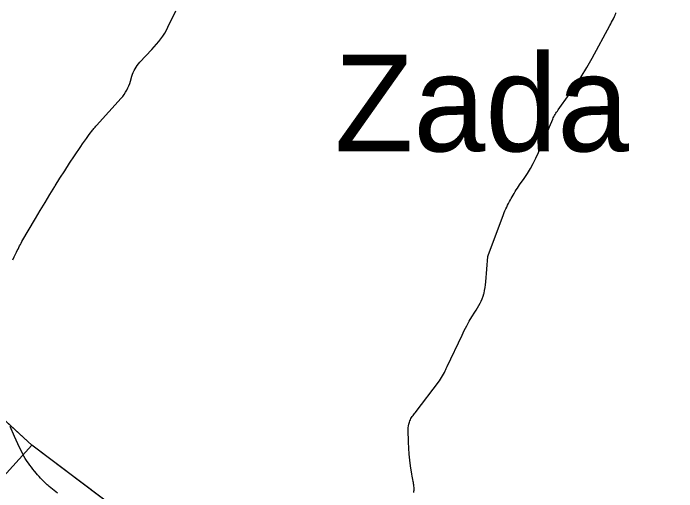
# Model space of a CAD drawing. Extents: x -629976 to -626966, y -1086511 to -1082952.
# Drawn here: x -629290.8 to -629174.2, y -1086163 to -1086079 of the extents above; entities that cross this region are included whole.
import ezdxf

# ---------------------------------------------------------------- set-up
doc = ezdxf.new("R2010")
doc.units = 0
for name, color, linetype in [('01_MÍSTNÍ_NÁZVY', 7, 'Continuous'), ('01_OBVOD PÚ', 7, 'Continuous'), ('01_SPRÁV_HRANICE', 7, 'Continuous'), ('01_VRSTEVNICE', 7, 'Continuous'), ('02_KULTURY STAV', 7, 'Continuous'), ('04_ZPF_OP_ORGAN', 7, 'Continuous')]:
    doc.layers.add(name, color=color, linetype=linetype)

msp = doc.modelspace()

# ---------------------------------------------------------------- linework, layer by layer
at = {"layer": '01_OBVOD PÚ'}
msp.add_lwpolyline([(-629018.08, -1086166.52), (-629041.66, -1086200.2), (-629067.51, -1086228.26), (-629069.33, -1086229.14), (-629087.1, -1086237.74), (-629120.75, -1086241.45), (-629122.84, -1086241.29), (-629134.67, -1086240.38), (-629143.31, -1086237.7), (-629155.05, -1086234.05), (-629163.08, -1086231.74), (-629174.67, -1086228.42), (-629203.15, -1086217.26), (-629215.64, -1086208.09), (-629217.4, -1086206.8), (-629237.51, -1086193.06), (-629238.46, -1086192.41), (-629270.92, -1086167.34), (-629287.56, -1086154.79), (-629303.24, -1086140.47)], dxfattribs=at)
at = {"layer": '01_SPRÁV_HRANICE'}
for p, q in [((-629287.56, -1086154.79), (-629303.24, -1086140.47)), ((-629270.92, -1086167.34), (-629287.56, -1086154.79))]:
    msp.add_line(p, q, dxfattribs=at)
msp.add_lwpolyline([(-629287.56, -1086154.79), (-629320.54, -1086191.18), (-629326.93, -1086197.96), (-629343.16, -1086215.19), (-629354.7, -1086227.44), (-629377.38, -1086206.8), (-629383.75, -1086214.59), (-629406.77, -1086242.76), (-629379.65, -1086273.09), (-629372.5, -1086281.08), (-629369.07, -1086285.03)], dxfattribs=at)
at = {"layer": '01_VRSTEVNICE'}
for points in [[(-629271.07, -1086092.84), (-629270.86, -1086092.46), (-629270.67, -1086092.07), (-629270.5, -1086091.67), (-629270.35, -1086091.27), (-629270.22, -1086090.85), (-629269.98, -1086090.01), (-629269.87, -1086089.67), (-629269.74, -1086089.34), (-629269.59, -1086089.02), (-629269.42, -1086088.7), (-629269.23, -1086088.4), (-629269.03, -1086088.11), (-629268.81, -1086087.83), (-629268.57, -1086087.57), (-629266.44, -1086085.3), (-629266.03, -1086084.85), (-629265.63, -1086084.4), (-629265.25, -1086083.93), (-629264.88, -1086083.46), (-629264.53, -1086082.97), (-629264.2, -1086082.47), (-629263.9, -1086081.95), (-629263.63, -1086081.42), (-629262.22, -1086078.5)], [(-629215.18, -1086142.37), (-629215.01, -1086142.05), (-629214.94, -1086141.92), (-629214.88, -1086141.78), (-629214.82, -1086141.65), (-629214.76, -1086141.51), (-629214.7, -1086141.37), (-629214.64, -1086141.24), (-629214.58, -1086141.1), (-629214.52, -1086140.97), (-629211.93, -1086135.5), (-629211.53, -1086134.67), (-629211.1, -1086133.85), (-629210.65, -1086133.05), (-629210.18, -1086132.26), (-629209.69, -1086131.47), (-629209.45, -1086131.08), (-629209.22, -1086130.69), (-629208.99, -1086130.29), (-629208.76, -1086129.9), (-629208.56, -1086129.5), (-629208.37, -1086129.09), (-629208.22, -1086128.66), (-629208.09, -1086128.23), (-629208.06, -1086128.13), (-629207.95, -1086127.63), (-629207.85, -1086127.14), (-629207.78, -1086126.64), (-629207.73, -1086126.14), (-629207.36, -1086121.66), (-629207.36, -1086121.64), (-629207.35, -1086121.61), (-629207.35, -1086121.59), (-629207.35, -1086121.56), (-629207.34, -1086121.55), (-629207.34, -1086121.53), (-629207.34, -1086121.51), (-629207.33, -1086121.5), (-629207.33, -1086121.48), (-629204.65, -1086114.31), (-629204.52, -1086113.97), (-629204.38, -1086113.64), (-629204.23, -1086113.32), (-629204.07, -1086112.99), (-629203.91, -1086112.67), (-629203.75, -1086112.35), (-629203.58, -1086112.04), (-629203.41, -1086111.72), (-629203.3, -1086111.51), (-629203.13, -1086111.2), (-629202.96, -1086110.89), (-629202.78, -1086110.59), (-629202.59, -1086110.28), (-629202.4, -1086109.98), (-629202.2, -1086109.69), (-629202, -1086109.39), (-629201.8, -1086109.1), (-629201.01, -1086107.98), (-629200.43, -1086107.12), (-629199.89, -1086106.24), (-629199.4, -1086105.32), (-629198.94, -1086104.39), (-629198.04, -1086102.42), (-629197.65, -1086101.54), (-629197.27, -1086100.67), (-629196.9, -1086099.78), (-629196.53, -1086098.9), (-629195.99, -1086097.56), (-629195.9, -1086097.34), (-629195.8, -1086097.13), (-629195.68, -1086096.92), (-629195.56, -1086096.72), (-629195.43, -1086096.52), (-629195.3, -1086096.32), (-629195.17, -1086096.12), (-629195.03, -1086095.93), (-629193.08, -1086093.23), (-629192, -1086091.68), (-629190.96, -1086090.09), (-629189.98, -1086088.47), (-629189.04, -1086086.82), (-629185.94, -1086081.12), (-629185.78, -1086080.82), (-629185.62, -1086080.52), (-629185.47, -1086080.22), (-629185.32, -1086079.92), (-629185.12, -1086079.51), (-629185.08, -1086079.41), (-629185.03, -1086079.31), (-629184.99, -1086079.21), (-629184.94, -1086079.1), (-629184.9, -1086079), (-629184.87, -1086078.89)], [(-629290.91, -1086122.25), (-629290.65, -1086121.71), (-629290.38, -1086121.15), (-629290.25, -1086120.89), (-629290.13, -1086120.62), (-629289.99, -1086120.36), (-629289.86, -1086120.1), (-629289.72, -1086119.83), (-629289.58, -1086119.58), (-629289.44, -1086119.32), (-629289.29, -1086119.06), (-629286.91, -1086115.02), (-629286.08, -1086113.6), (-629285.23, -1086112.19), (-629284.38, -1086110.78), (-629283.53, -1086109.38), (-629283.44, -1086109.24), (-629282.61, -1086107.91), (-629281.78, -1086106.6), (-629280.92, -1086105.29), (-629280.06, -1086103.99), (-629278.97, -1086102.38), (-629278.63, -1086101.9), (-629278.3, -1086101.41), (-629277.96, -1086100.93), (-629277.61, -1086100.45), (-629277.14, -1086099.8), (-629277.03, -1086099.65), (-629276.91, -1086099.51), (-629276.79, -1086099.36), (-629276.67, -1086099.22), (-629276.55, -1086099.07), (-629276.43, -1086098.93), (-629276.3, -1086098.79), (-629276.18, -1086098.65), (-629271.84, -1086093.88), (-629271.56, -1086093.55), (-629271.3, -1086093.2), (-629271.07, -1086092.84)], [(-629220.42, -1086163.14), (-629220.39, -1086162.92), (-629220.36, -1086162.7), (-629220.36, -1086162.48), (-629220.36, -1086162.25), (-629220.38, -1086162.03), (-629220.41, -1086161.8), (-629220.44, -1086161.58), (-629220.48, -1086161.36), (-629220.52, -1086161.18), (-629220.58, -1086160.87), (-629220.64, -1086160.55), (-629220.69, -1086160.24), (-629220.74, -1086159.92), (-629220.97, -1086158.47), (-629221.11, -1086157.43), (-629221.23, -1086156.38), (-629221.3, -1086155.33), (-629221.35, -1086154.28), (-629221.4, -1086152.12), (-629221.39, -1086151.78), (-629221.35, -1086151.44), (-629221.28, -1086151.11), (-629221.18, -1086150.78), (-629221.09, -1086150.54), (-629221.01, -1086150.34), (-629220.91, -1086150.15), (-629220.8, -1086149.97), (-629220.67, -1086149.79), (-629220.54, -1086149.62), (-629220.41, -1086149.45), (-629220.27, -1086149.28), (-629220.14, -1086149.11), (-629215.89, -1086143.49), (-629215.7, -1086143.22), (-629215.51, -1086142.95), (-629215.34, -1086142.66), (-629215.18, -1086142.37)], [(-629283.05, -1086163.25), (-629284.54, -1086162.05), (-629284.7, -1086161.91), (-629284.86, -1086161.77), (-629285.02, -1086161.63), (-629285.17, -1086161.49), (-629285.32, -1086161.34), (-629285.47, -1086161.19), (-629285.62, -1086161.04), (-629285.76, -1086160.88), (-629286.02, -1086160.61), (-629286.28, -1086160.32), (-629286.54, -1086160.03), (-629286.8, -1086159.72), (-629287.05, -1086159.42), (-629287.1, -1086159.37), (-629287.36, -1086159.03), (-629287.63, -1086158.69), (-629287.89, -1086158.35), (-629288.15, -1086158), (-629288.2, -1086157.92), (-629288.47, -1086157.53), (-629288.73, -1086157.13), (-629288.97, -1086156.72), (-629289.19, -1086156.3), (-629289.4, -1086155.88), (-629289.72, -1086155.24), (-629290.02, -1086154.6), (-629290.32, -1086153.95), (-629290.61, -1086153.3), (-629291.36, -1086151.55)]]:
    msp.add_lwpolyline(points, dxfattribs=at)
at = {"layer": '02_KULTURY STAV'}
msp.add_lwpolyline([(-629029.73, -1086183.16), (-629041.66, -1086200.2), (-629067.51, -1086228.26), (-629069.33, -1086229.14), (-629087.1, -1086237.74), (-629120.75, -1086241.45), (-629122.84, -1086241.29), (-629126.85, -1086240.98), (-629134.67, -1086240.38), (-629143.31, -1086237.7), (-629155.05, -1086234.05), (-629163.08, -1086231.74), (-629174.67, -1086228.42), (-629184.25, -1086224.67), (-629203.15, -1086217.26), (-629215.64, -1086208.09), (-629217.4, -1086206.8), (-629237.51, -1086193.06), (-629238.46, -1086192.41), (-629270.92, -1086167.34), (-629287.56, -1086154.79), (-629303.24, -1086140.47)], dxfattribs=at)
at = {"layer": '04_ZPF_OP_ORGAN'}
msp.add_lwpolyline([(-629029.73, -1086183.16), (-629041.66, -1086200.2), (-629067.51, -1086228.26), (-629069.33, -1086229.14), (-629087.1, -1086237.74), (-629120.75, -1086241.45), (-629122.84, -1086241.29), (-629126.85, -1086240.98), (-629134.67, -1086240.38), (-629143.31, -1086237.7), (-629155.05, -1086234.05), (-629163.08, -1086231.74), (-629174.67, -1086228.42), (-629184.25, -1086224.67), (-629203.15, -1086217.26), (-629215.64, -1086208.09), (-629217.4, -1086206.8), (-629237.51, -1086193.06), (-629238.46, -1086192.41), (-629270.92, -1086167.34), (-629287.56, -1086154.79), (-629303.24, -1086140.47)], dxfattribs=at)

# ---------------------------------------------------------------- texts
at = {"layer": '01_MÍSTNÍ_NÁZVY'}
msp.add_text('Zada', height=17, dxfattribs=at).set_placement((-629234.36, -1086103.21))

doc.saveas('drawing.dxf')
